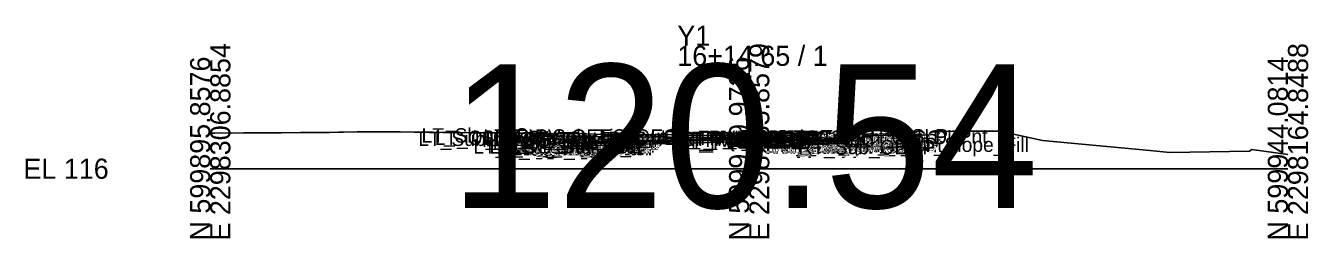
# Model space of a CAD drawing. Extents: x -26 to 2453, y -10 to 6530.
# Drawn here: x 2274.3 to 2452.8, y -9.7 to 19.9 of the extents above; entities that cross this region are included whole.
import ezdxf

# ---------------------------------------------------------------- set-up
doc = ezdxf.new("R2010")
doc.units = 0
for name, color, linetype in [('Default', 7, 'Continuous'), ('Exist CMT Pavement', 7, 'Continuous'), ('Exist Cross Section Cell', 7, 'Continuous'), ('Exist XS Ground Line', 7, 'Continuous'), ('Prop CMT Conc Surface', 7, 'Continuous'), ('Prop CMT Concrete Structures', 7, 'Continuous'), ('Prop CMT Pvmt Course 1', 7, 'Continuous'), ('Prop CMT Pvmt Course 1 CG', 7, 'Continuous'), ('Prop CMT Pvmt Course 1 Wedge', 7, 'Continuous'), ('Prop CMT Pvmt Course 2', 7, 'Continuous'), ('Prop CMT Pvmt Course 2 Wedge', 7, 'Continuous'), ('Prop CMT Pvmt Course 3', 7, 'Continuous'), ('Prop CMT Pvmt Course 3 Wedge', 7, 'Continuous'), ('Prop CMT Pvmt Surface', 7, 'Continuous'), ('Prop CMT Pvmt Wedge Surface 1', 7, 'Continuous'), ('Prop CMT Pvmt Wedge Surface 2', 7, 'Continuous'), ('Prop CMT Pvmt Wedge Surface 3', 7, 'Continuous'), ('Prop CMT Slope Grass', 7, 'Continuous'), ('Prop CMT Subgrade Earthwork', 7, 'Continuous')]:
    doc.layers.add(name, color=color, linetype=linetype)

msp = doc.modelspace()

# ---------------------------------------------------------------- linework, layer by layer
at = {"layer": 'Exist CMT Pavement'}
for points in [[(2375.01, 4.28), (2353.06, 4.48)], [(2375.01, 4.28), (2388.99, 3.83)]]:
    msp.add_lwpolyline(points, dxfattribs=at)
at = {"layer": 'Exist Cross Section Cell'}
for p, q in [((2375.01, 0), (2375.01, 17.11)), ((2300, 0), (2375.01, 0)), ((2375.01, 0), (2450, 0))]:
    msp.add_line(p, q, dxfattribs=at)
at = {"layer": 'Exist XS Ground Line'}
msp.add_lwpolyline([(2300, 4.94), (2300.57, 4.95), (2301.61, 4.97), (2302.94, 4.95), (2304.63, 4.97), (2305.11, 4.97), (2306.72, 4.98), (2307.27, 4.98), (2308.38, 4.99), (2309.91, 5.01), (2312.55, 5.04), (2312.88, 5.04), (2315.19, 5.05), (2316.58, 5.06), (2317.83, 5.07), (2318.55, 5.08), (2320.47, 5.11), (2322.02, 5.12), (2322.99, 5.15), (2323.71, 5.11), (2324.37, 5.12), (2325.75, 5.13), (2326.43, 5.12), (2328.44, 5.09), (2331.03, 5.07), (2332.35, 5.05), (2333.67, 5.04), (2334.32, 5.03), (2336.31, 5.01), (2338.26, 5), (2338.95, 4.99), (2340.36, 4.99), (2340.99, 4.99), (2342.11, 4.98), (2343.17, 4.96), (2344.36, 4.95), (2345.87, 4.92), (2346.85, 4.83), (2347.72, 4.89), (2348.36, 4.9), (2349.51, 4.88), (2351.77, 4.84), (2352.35, 4.83), (2354.79, 4.75), (2356.35, 4.73), (2357.43, 4.7), (2357.97, 4.7), (2359.54, 4.73), (2360.07, 4.73), (2361.91, 4.75), (2362.71, 4.74), (2364.35, 4.73), (2365.35, 4.72), (2367.32, 4.68), (2368, 4.67), (2368.34, 4.67), (2370.64, 4.64), (2371.64, 4.62), (2372.19, 4.57), (2373.28, 4.59), (2375.09, 4.54), (2375.92, 4.52), (2376.34, 4.5), (2378.56, 4.44), (2380.33, 4.4), (2381.2, 4.38), (2382.87, 4.35), (2383.84, 4.33), (2384.33, 4.32), (2386.48, 4.26), (2387.86, 4.2), (2388.64, 4.15), (2390.02, 4.12), (2390.42, 4.11), (2391.12, 4.63), (2391.85, 4.66), (2392.24, 4.67), (2396.51, 4.65), (2399.81, 4.72), (2399.87, 4.58), (2400.37, 5.09), (2403.32, 5.23), (2409.92, 5.22), (2415.82, 3.94), (2430.78, 2.55), (2433.57, 2.27), (2444.67, 2.44), (2444.98, 2.69), (2450, 1.98)], dxfattribs=at)
at = {"layer": 'Prop CMT Conc Surface'}
for points in [[(2351.06, 3.61), (2351.06, 4.11), (2350.56, 4.11)], [(2353.06, 3.74), (2351.06, 3.61)], [(2388.51, 3.95), (2390.51, 3.82)], [(2390.51, 3.82), (2390.51, 4.32), (2391.01, 4.32)]]:
    msp.add_lwpolyline(points, dxfattribs=at)
at = {"layer": 'Prop CMT Concrete Structures'}
for points in [[(2353.06, 3.74), (2351.06, 3.61), (2351.06, 4.11), (2350.56, 4.11)], [(2350.56, 4.11), (2350.56, 3.1), (2353.06, 3.16)], [(2353.06, 3.16), (2353.06, 3.74)], [(2388.51, 3.95), (2390.51, 3.82), (2390.51, 4.32), (2391.01, 4.32)], [(2391.01, 4.32), (2391.01, 3.31), (2388.51, 3.37)], [(2388.51, 3.37), (2388.51, 3.95)]]:
    msp.add_lwpolyline(points, dxfattribs=at)
at = {"layer": 'Prop CMT Pvmt Course 1'}
for points in [[(2375.01, 4.29), (2353.06, 3.74)], [(2353.06, 3.62), (2375.01, 4.17)], [(2353.06, 3.74), (2353.06, 3.49), (2353.06, 3.49), (2353.06, 3.62)], [(2375.01, 4.04), (2375.01, 4.29)], [(2375.01, 4.29), (2388.51, 3.95)], [(2375.01, 4.04), (2375.01, 4.29)], [(2375.01, 4.17), (2375.01, 4.04), (2375.01, 4.04)], [(2388.99, 3.82), (2375.01, 4.17)], [(2375.01, 4.17), (2375.01, 4.04), (2375.01, 4.04)], [(2388.51, 3.95), (2388.51, 3.7)], [(2388.51, 3.7), (2388.99, 3.69)], [(2388.99, 3.69), (2388.99, 3.82)]]:
    msp.add_lwpolyline(points, dxfattribs=at)
at = {"layer": 'Prop CMT Pvmt Course 1 CG'}
for points in [[(2353.06, 3.16), (2350.06, 3.08), (2349.76, 2.79)], [(2349.76, 2.79), (2353.06, 2.87)], [(2353.06, 2.87), (2353.06, 3.16)], [(2388.51, 3.37), (2391.51, 3.3), (2391.81, 3)], [(2388.51, 3.08), (2388.51, 3.37)], [(2391.81, 3), (2388.51, 3.08)]]:
    msp.add_lwpolyline(points, dxfattribs=at)
at = {"layer": 'Prop CMT Pvmt Course 1 Wedge'}
for points in [[(2375.01, 4.17), (2353.06, 3.62)], [(2375.01, 4.17), (2388.99, 3.82)]]:
    msp.add_lwpolyline(points, dxfattribs=at)
at = {"layer": 'Prop CMT Pvmt Course 2'}
for points in [[(2388.99, 3.69), (2388.51, 3.7)], [(2388.51, 3.7), (2388.51, 3.45)], [(2388.99, 3.44), (2388.99, 3.69)], [(2353.06, 3.24), (2353.06, 3.24), (2353.06, 3.49), (2353.06, 3.49)], [(2353.06, 3.49), (2353.06, 3.24)], [(2388.51, 3.45), (2388.99, 3.44)]]:
    msp.add_lwpolyline(points, dxfattribs=at)
at = {"layer": 'Prop CMT Pvmt Course 2 Wedge'}
for points in [[(2375.01, 4.04), (2353.06, 3.49)], [(2375.01, 4.04), (2388.99, 3.69)]]:
    msp.add_lwpolyline(points, dxfattribs=at)
at = {"layer": 'Prop CMT Pvmt Course 3'}
for points in [[(2353.06, 3.24), (2353.06, 3.24), (2353.06, 2.87), (2353.06, 2.87)], [(2353.06, 2.87), (2353.06, 3.24)], [(2388.99, 3.44), (2388.51, 3.45)], [(2388.51, 3.45), (2388.51, 3.08)], [(2388.51, 3.08), (2388.99, 3.07)], [(2388.99, 3.07), (2388.99, 3.44)]]:
    msp.add_lwpolyline(points, dxfattribs=at)
at = {"layer": 'Prop CMT Pvmt Course 3 Wedge'}
msp.add_line((2396.12, 4.73), (2396.12, 4.58), dxfattribs=at)
for points in [[(2375.01, 3.79), (2353.06, 3.24)], [(2375.01, 3.79), (2388.99, 3.44)]]:
    msp.add_lwpolyline(points, dxfattribs=at)
at = {"layer": 'Prop CMT Pvmt Surface'}
for points in [[(2375.01, 4.29), (2353.06, 3.74)], [(2375.01, 4.29), (2388.51, 3.95)]]:
    msp.add_lwpolyline(points, dxfattribs=at)
at = {"layer": 'Prop CMT Pvmt Wedge Surface 1'}
for points in [[(2375.01, 4.17), (2353.06, 3.62)], [(2353.06, 3.49), (2353.06, 3.74)], [(2353.06, 3.62), (2353.06, 3.49), (2353.06, 3.49)], [(2375.01, 4.17), (2388.99, 3.82)], [(2388.51, 3.7), (2388.51, 3.95)], [(2388.99, 3.69), (2388.51, 3.7)], [(2388.99, 3.82), (2388.99, 3.69)]]:
    msp.add_lwpolyline(points, dxfattribs=at)
at = {"layer": 'Prop CMT Pvmt Wedge Surface 2'}
for points in [[(2375.01, 4.04), (2353.06, 3.49)], [(2353.06, 3.49), (2353.06, 3.74)], [(2375.01, 4.04), (2388.51, 3.7)], [(2388.51, 3.7), (2388.51, 3.95)]]:
    msp.add_lwpolyline(points, dxfattribs=at)
at = {"layer": 'Prop CMT Pvmt Wedge Surface 3'}
for points in [[(2375.01, 3.79), (2353.06, 3.24)], [(2353.06, 3.24), (2353.06, 3.74)], [(2375.01, 3.79), (2388.51, 3.45)], [(2388.51, 3.45), (2388.51, 3.95)]]:
    msp.add_lwpolyline(points, dxfattribs=at)
at = {"layer": 'Prop CMT Slope Grass'}
for points in [[(2350.56, 4.11), (2341.06, 4.3), (2339.78, 4.63)], [(2391.12, 4.63), (2396.12, 4.73)]]:
    msp.add_lwpolyline(points, dxfattribs=at)
at = {"layer": 'Prop CMT Subgrade Earthwork'}
for points in [[(2353.06, 2.87), (2349.76, 2.79), (2348.39, 4.16)], [(2353.06, 2.87), (2353.08, 4.48)], [(2388.51, 3.08), (2391.81, 3), (2393.18, 4.37)], [(2388.99, 3.07), (2388.97, 3.83)], [(2353.06, 2.87), (2353.06, 2.87)], [(2388.99, 3.07), (2388.51, 3.08)]]:
    msp.add_lwpolyline(points, dxfattribs=at)

# ---------------------------------------------------------------- texts
at = {"layer": 'Default'}
for s, height, p in [('120.54', 20, (2333.43, -5.46)), ('LT_Slope_Cut', 2, (2329.41, 3.63)), ('LT_PV_Sub_Tie_Out', 2, (2338.02, 3.48)), ('LT_PV_OEEOP_EG', 2, (2340.61, 3.48)), ('RT_Sub_Trench_Out_DLT', 2, (2373.7, 3.37)), ('RT_CSLP_Pnt', 2, (2390.64, 3.51)), ('LT_Sub_Trench_Out_DLT', 2, (2328.96, 3.16)), ('LT_CSLP_Pnt', 2, (2331.24, 3.3)), ('LT_CG1_Shelf_Out', 2, (2336.61, 2.08)), ('LT_CG_Top_Face', 2, (2338.32, 3.11)), ('LT_CG_Top_BOC', 2, (2338.85, 3.11)), ('LT_CG_Bot_BOC', 2, (2338.88, 2.1)), ('LT_CG_Top_Gut', 2, (2339.3, 2.61)), ('LT_Sub_OEOP', 2, (2339.87, 1.79)), ('LT_Sub_OEEOP', 2, (2342.28, 1.87)), ('LT_PV2_OEEOP', 2, (2342.37, 2.49)), ('LT_PV3_OEEOP', 2, (2342.37, 2.24)), ('LT_PV1_OEEOP', 2, (2342.94, 2.62)), ('LT_CG_Bot_IE', 2, (2342.98, 2.16)), ('LT_Sub_OEOT', 2, (2343.14, 1.87)), ('LT_PV2_OEOT', 2, (2343.24, 2.49)), ('LT_PV3_OEOT', 2, (2343.24, 2.24)), ('LT_PV1_OEOT', 2, (2343.8, 2.74)), ('RT_PV_IEEOP_EG', 2, (2363.15, 3.28)), ('LT_PV_IEEOP_EG', 2, (2363.2, 3.28)), ('RT_PV2_IEEOP', 2, (2364.92, 3.04)), ('RT_PV3_IEEOP', 2, (2364.92, 2.79)), ('LT_PV2_IEEOP', 2, (2364.96, 3.04)), ('LT_PV3_IEEOP', 2, (2364.96, 2.79)), ('RT_PV1_IEEOP', 2, (2365.48, 3.17)), ('LT_PV1_IEEOP', 2, (2365.53, 3.17)), ('PV2_PGL', 2, (2368.92, 3.04)), ('PV1_PGL', 2, (2369.48, 3.29)), ('RT_PV_Sub_Tie_Out', 2, (2373.87, 2.83)), ('RT_PV_OEEOP_EG', 2, (2376.49, 2.83)), ('RT_CG_Top_Face', 2, (2377.72, 3.32)), ('RT_CG1_Shelf_Out', 2, (2378.01, 2.3)), ('RT_Sub_OEEOP', 2, (2378.16, 2.07)), ('RT_PV2_OEEOP', 2, (2378.25, 2.69)), ('RT_PV3_OEEOP', 2, (2378.25, 2.44)), ('RT_CG_Bot_IE', 2, (2378.38, 2.37)), ('RT_Sub_OEOT', 2, (2378.54, 2.08)), ('RT_PV2_OEOT', 2, (2378.64, 2.7)), ('RT_PV3_OEOT', 2, (2378.64, 2.45)), ('RT_CG_Top_Gut', 2, (2378.7, 2.82)), ('RT_PV1_OEEOP', 2, (2378.82, 2.82)), ('RT_PV1_OEOT', 2, (2379.2, 2.95)), ('RT_CG_Top_BOC', 2, (2379.25, 3.32)), ('RT_CG_Bot_BOC', 2, (2379.28, 2.31)), ('RT_Sub_OEOP', 2, (2381.87, 2)), ('RT_Slope_Fill', 2, (2397.16, 2.34)), ('-', 0.0001, (2300, 0))]:
    msp.add_text(s, height=height, dxfattribs=at).set_placement(p)
at = {"layer": 'Exist Cross Section Cell'}
for s, p in [('Y1', (2365.01, 17.11)), ('16+14.65 / 1', (2365.01, 14.31)), ('EL 116', (2274, -1.4))]:
    msp.add_text(s, height=2.8, dxfattribs=at).set_placement(p)
for s, p in [('E 2298306.8854', (2302.8, -10)), ('E 2298235.8579', (2377.81, -10)), ('E 2298164.8488', (2452.8, -10)), ('N 599895.8576', (2300, -10)), ('N 599919.9726', (2375.01, -10)), ('N 599944.0814', (2450, -10))]:
    msp.add_text(s, height=2.8, rotation=90, dxfattribs=at).set_placement(p)

doc.saveas('drawing.dxf')
